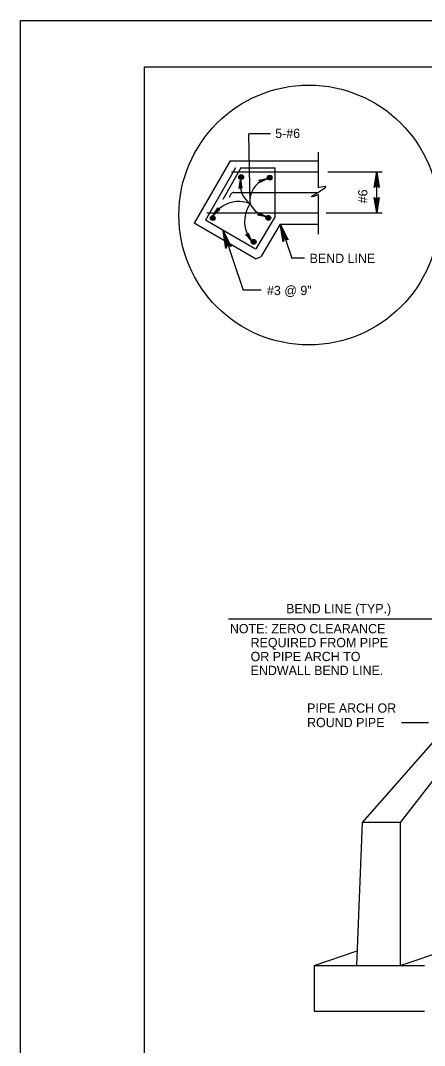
# Model space of a CAD drawing. Extents: x 639011 to 639866, y 298840 to 300028.
# Drawn here: x 639011.3 to 639141.6, y 299696.8 to 300027.8 of the extents above; entities that cross this region are included whole.
import ezdxf

# ---------------------------------------------------------------- set-up
doc = ezdxf.new("R2010")
doc.units = 0
doc.layers.add('2', color=7, linetype='Continuous')
doc.layers.add('PLT-BNDY', color=7, linetype='Continuous')

msp = doc.modelspace()

# ---------------------------------------------------------------- linework, layer by layer
at = {"layer": '2'}
for p, q in [((639051.26, 299448.83), (639051.26, 300012.83)), ((639051.26, 300012.83), (639837.26, 300012.83)), ((639091.9, 299991.23), (639084.97, 299991.23)), ((639085.32, 299968.69), (639084.97, 299991.23)), ((639107.44, 299973.84), (639107.44, 299985.29)), ((639078.85, 299982.54), (639067.3, 299962.41)), ((639078.85, 299982.54), (639107.4, 299982.54)), ((639080.65, 299980.29), (639070.96, 299963.4)), ((639082.36, 299980.25), (639076.52, 299970.07)), ((639079.34, 299978.93), (639107.48, 299978.93)), ((639082.36, 299980.25), (639093.45, 299980.25)), ((639093.42, 299964.61), (639093.42, 299980.25)), ((639110.38, 299978.93), (639127.92, 299978.93)), ((639125.4, 299973.91), (639126.18, 299978.93)), ((639126.18, 299978.93), (639125.61, 299974.17)), ((639125.96, 299974.35), (639126.18, 299978.93)), ((639126.18, 299965.69), (639126.18, 299978.93)), ((639126.18, 299978.93), (639126.44, 299974.35)), ((639126.78, 299974.18), (639126.18, 299978.93)), ((639126.18, 299978.93), (639127.02, 299973.92)), ((639126.18, 299978.93), (639126.2, 299974.35)), ((639079.15, 299971.77), (639078.55, 299970.71)), ((639080.1, 299972.31), (639106.93, 299972.31)), ((639107.44, 299958.87), (639107.44, 299971.56)), ((639125.61, 299974.17), (639125.4, 299973.91)), ((639125.61, 299974.17), (639125.96, 299974.35)), ((639125.96, 299974.35), (639126.44, 299974.35)), ((639126.44, 299974.35), (639126.78, 299974.18)), ((639127.02, 299973.92), (639126.78, 299974.18)), ((639126.18, 299965.69), (639125.34, 299970.7)), ((639125.34, 299970.7), (639125.58, 299970.44)), ((639125.92, 299970.27), (639125.58, 299970.44)), ((639125.58, 299970.44), (639126.18, 299965.69)), ((639126.18, 299965.69), (639125.92, 299970.27)), ((639126.4, 299970.27), (639125.92, 299970.27)), ((639126.18, 299965.69), (639126.16, 299970.27)), ((639126.96, 299970.71), (639126.18, 299965.69)), ((639126.18, 299965.69), (639126.75, 299970.45)), ((639126.4, 299970.27), (639126.18, 299965.69)), ((639126.75, 299970.45), (639126.4, 299970.27)), ((639126.75, 299970.45), (639126.96, 299970.71)), ((639071.33, 299965.69), (639107.32, 299965.69)), ((639109.88, 299965.69), (639127.92, 299965.69)), ((639087.1, 299950.86), (639067.3, 299962.41)), ((639087.1, 299953.97), (639070.95, 299963.39)), ((639093.37, 299964.56), (639087.13, 299954.05)), ((639095.02, 299962.08), (639088.75, 299951.52)), ((639095.02, 299962.08), (639107.48, 299962.08)), ((639095.19, 299961.9), (639098.84, 299951.12)), ((639076.6, 299959.94), (639083.1, 299940.76)), ((639087.1, 299950.86), (639088.75, 299951.52)), ((639102.87, 299951.03), (639098.59, 299951.03)), ((639088.85, 299940.76), (639083.1, 299940.76)), ((639078.36, 299834.64), (639158.56, 299834.64)), ((639142.87, 299801.01), (639134.13, 299801.01)), ((639145.92, 299796.64), (639121.54, 299768.89)), ((639155.29, 299796.64), (639133.73, 299768.89)), ((639121.54, 299768.89), (639119.67, 299722.71)), ((639133.73, 299768.89), (639121.54, 299768.89)), ((639133.73, 299768.89), (639133.73, 299722.71)), ((639133.73, 299722.71), (639155.67, 299730.02)), ((639105.98, 299722.71), (639119.85, 299727.39)), ((639105.98, 299722.71), (639105.98, 299707.89)), ((639105.98, 299722.71), (639141.61, 299722.71)), ((639105.98, 299707.89), (639141.58, 299707.89))]:
    msp.add_line(p, q, dxfattribs=at)
for points in [[(639082, 299973.8), (639082.12, 299973.91), (639082.28, 299976.48), (639082, 299973.8), (639081.82, 299973.63), (639082.28, 299976.48), (639082.41, 299973.97), (639082.58, 299973.79), (639082.28, 299976.48), (639082.7, 299973.67), (639082.58, 299973.79)], [(639088.32, 299976.19), (639088.47, 299976.11), (639090.93, 299976.84), (639088.32, 299976.19), (639088.1, 299976.3), (639090.93, 299976.84), (639088.62, 299975.86), (639088.51, 299975.64), (639090.93, 299976.84), (639088.44, 299975.49), (639088.51, 299975.64)], [(639075.36, 299966.81), (639075.2, 299966.79), (639073.46, 299964.9), (639075.36, 299966.81), (639075.61, 299966.83), (639073.46, 299964.9), (639074.94, 299966.93), (639074.91, 299967.18), (639073.46, 299964.9), (639074.9, 299967.35), (639074.91, 299967.18)], [(639088.05, 299965.63), (639088.11, 299965.48), (639090.49, 299964.49), (639088.05, 299965.63), (639087.94, 299965.85), (639090.49, 299964.49), (639088.07, 299965.18), (639087.85, 299965.08), (639090.49, 299964.49), (639087.7, 299965.01), (639087.85, 299965.08)], [(639096.19, 299956.77), (639096.34, 299957.06), (639095.06, 299962.04), (639096.19, 299956.77), (639095.95, 299956.33), (639095.06, 299962.04), (639096.86, 299957.34), (639097.3, 299957.11), (639095.06, 299962.04), (639097.59, 299956.96), (639097.3, 299957.11)], [(639077.76, 299954.65), (639077.92, 299954.94), (639076.64, 299959.92), (639077.76, 299954.65), (639077.53, 299954.21), (639076.64, 299959.92), (639078.44, 299955.22), (639078.88, 299954.99), (639076.64, 299959.92), (639079.17, 299954.84), (639078.88, 299954.99)], [(639084.54, 299959.04), (639084.5, 299958.88), (639085.8, 299956.67), (639084.54, 299959.04), (639084.59, 299959.28), (639085.8, 299956.67), (639084.29, 299958.67), (639084.05, 299958.72), (639085.8, 299956.67), (639083.89, 299958.76), (639084.05, 299958.72)]]:
    msp.add_lwpolyline(points, dxfattribs=at)
for centre, radius in [((639104.3, 299965.01), 41.95), ((639082.45, 299977.28), 0.777), ((639082.45, 299977.28), 0.777), ((639082.45, 299977.28), 0.777), ((639082.45, 299977.28), 0.777), ((639082.45, 299977.28), 0.777), ((639082.45, 299977.28), 0.777), ((639082.45, 299977.27), 0.629), ((639082.45, 299977.27), 0.629), ((639082.45, 299977.27), 0.496), ((639082.45, 299977.27), 0.496), ((639082.45, 299977.26), 0.348), ((639082.45, 299977.26), 0.348), ((639082.45, 299977.28), 0.19), ((639082.45, 299977.28), 0.19), ((639082.47, 299977.27), 0.0536), ((639082.47, 299977.27), 0.0536), ((639091.67, 299977.08), 0.777), ((639091.67, 299977.08), 0.777), ((639091.67, 299977.08), 0.777), ((639091.67, 299977.08), 0.777), ((639091.67, 299977.08), 0.777), ((639091.67, 299977.08), 0.777), ((639091.67, 299977.07), 0.629), ((639091.67, 299977.07), 0.629), ((639091.67, 299977.07), 0.496), ((639091.67, 299977.07), 0.496), ((639091.67, 299977.05), 0.348), ((639091.67, 299977.05), 0.348), ((639091.67, 299977.08), 0.19), ((639091.67, 299977.08), 0.19), ((639091.68, 299977.07), 0.0536), ((639091.68, 299977.07), 0.0536), ((639091.2, 299964.1), 0.777), ((639091.2, 299964.1), 0.777), ((639091.2, 299964.1), 0.777), ((639091.2, 299964.1), 0.777), ((639091.2, 299964.1), 0.777), ((639091.2, 299964.1), 0.777), ((639073.28, 299964.02), 0.777), ((639073.28, 299964.02), 0.777), ((639073.28, 299964.02), 0.777), ((639073.28, 299964.02), 0.777), ((639073.28, 299964.02), 0.777), ((639073.28, 299964.02), 0.777), ((639073.28, 299964.01), 0.629), ((639073.28, 299964.01), 0.629), ((639073.28, 299964.01), 0.496), ((639073.28, 299964.01), 0.496), ((639073.28, 299963.99), 0.348), ((639073.28, 299963.99), 0.348), ((639073.28, 299964.02), 0.19), ((639073.28, 299964.02), 0.19), ((639073.3, 299964.01), 0.0536), ((639073.3, 299964.01), 0.0536), ((639091.21, 299964.09), 0.629), ((639091.21, 299964.09), 0.629), ((639091.21, 299964.09), 0.496), ((639091.21, 299964.09), 0.496), ((639091.21, 299964.08), 0.348), ((639091.21, 299964.08), 0.348), ((639091.21, 299964.1), 0.19), ((639091.21, 299964.1), 0.19), ((639091.22, 299964.09), 0.0536), ((639091.22, 299964.09), 0.0536), ((639086.49, 299956.36), 0.777), ((639086.49, 299956.36), 0.777), ((639086.49, 299956.36), 0.777), ((639086.49, 299956.36), 0.777), ((639086.49, 299956.36), 0.777), ((639086.49, 299956.36), 0.777), ((639086.49, 299956.35), 0.629), ((639086.49, 299956.35), 0.629), ((639086.49, 299956.35), 0.496), ((639086.49, 299956.35), 0.496), ((639086.49, 299956.34), 0.348), ((639086.49, 299956.34), 0.348), ((639086.49, 299956.36), 0.19), ((639086.49, 299956.36), 0.19), ((639086.51, 299956.35), 0.0536), ((639086.51, 299956.35), 0.0536)]:
    msp.add_circle(centre, radius, dxfattribs=at)
for centre, radius, start, end in [((639089.54, 299974.86), 7.44, 166.9714, 236.1955), ((639092.72, 299969.63), 7.44, 95.8698, 187.6846), ((639080.06, 299971.3), 1.01, 87.502, 152.6316), ((639081.7, 299959.47), 9.9, 68.5124, 149.5829), ((639093.44, 299963.02), 9.9, 145.0546, 221.686), ((639092.09, 299971.77), 7.44, 204.539, 262.6579)]:
    msp.add_arc(centre, radius, start, end, dxfattribs=at)
msp.add_spline([(639107.46, 299971.54), (639105.15, 299970.88), (639109.77, 299974.18), (639107.46, 299973.85)], degree=3, dxfattribs=at)
at = {"layer": 'PLT-BNDY'}
msp.add_lwpolyline([(639011.26, 300027.83), (639852.26, 300027.83), (639852.26, 299433.83), (639011.26, 299433.83)], close=True, dxfattribs=at)

# ---------------------------------------------------------------- texts
at = {"layer": '2'}
for s, p in [('5-#6', (639093.43, 299989.88)), ('BEND LINE', (639104.53, 299949.53)), ('#3 @ 9"', (639090.78, 299939.16)), ('BEND LINE (TYP.)', (639096.96, 299836.41)), ('NOTE: ZERO CLEARANCE', (639078.81, 299829.95)), ('      REQUIRED FROM PIPE', (639078.81, 299825.45)), ('      OR PIPE ARCH TO', (639078.81, 299820.95)), ('      ENDWALL BEND LINE.', (639078.81, 299816.45)), ('PIPE ARCH OR ', (639103.71, 299804.3)), ('ROUND PIPE', (639103.71, 299799.64))]:
    msp.add_text(s, height=3, dxfattribs=at).set_placement(p)
msp.add_text('#6', height=3, rotation=90, dxfattribs=at).set_placement((639123.19, 299968.81))

doc.saveas('drawing.dxf')
